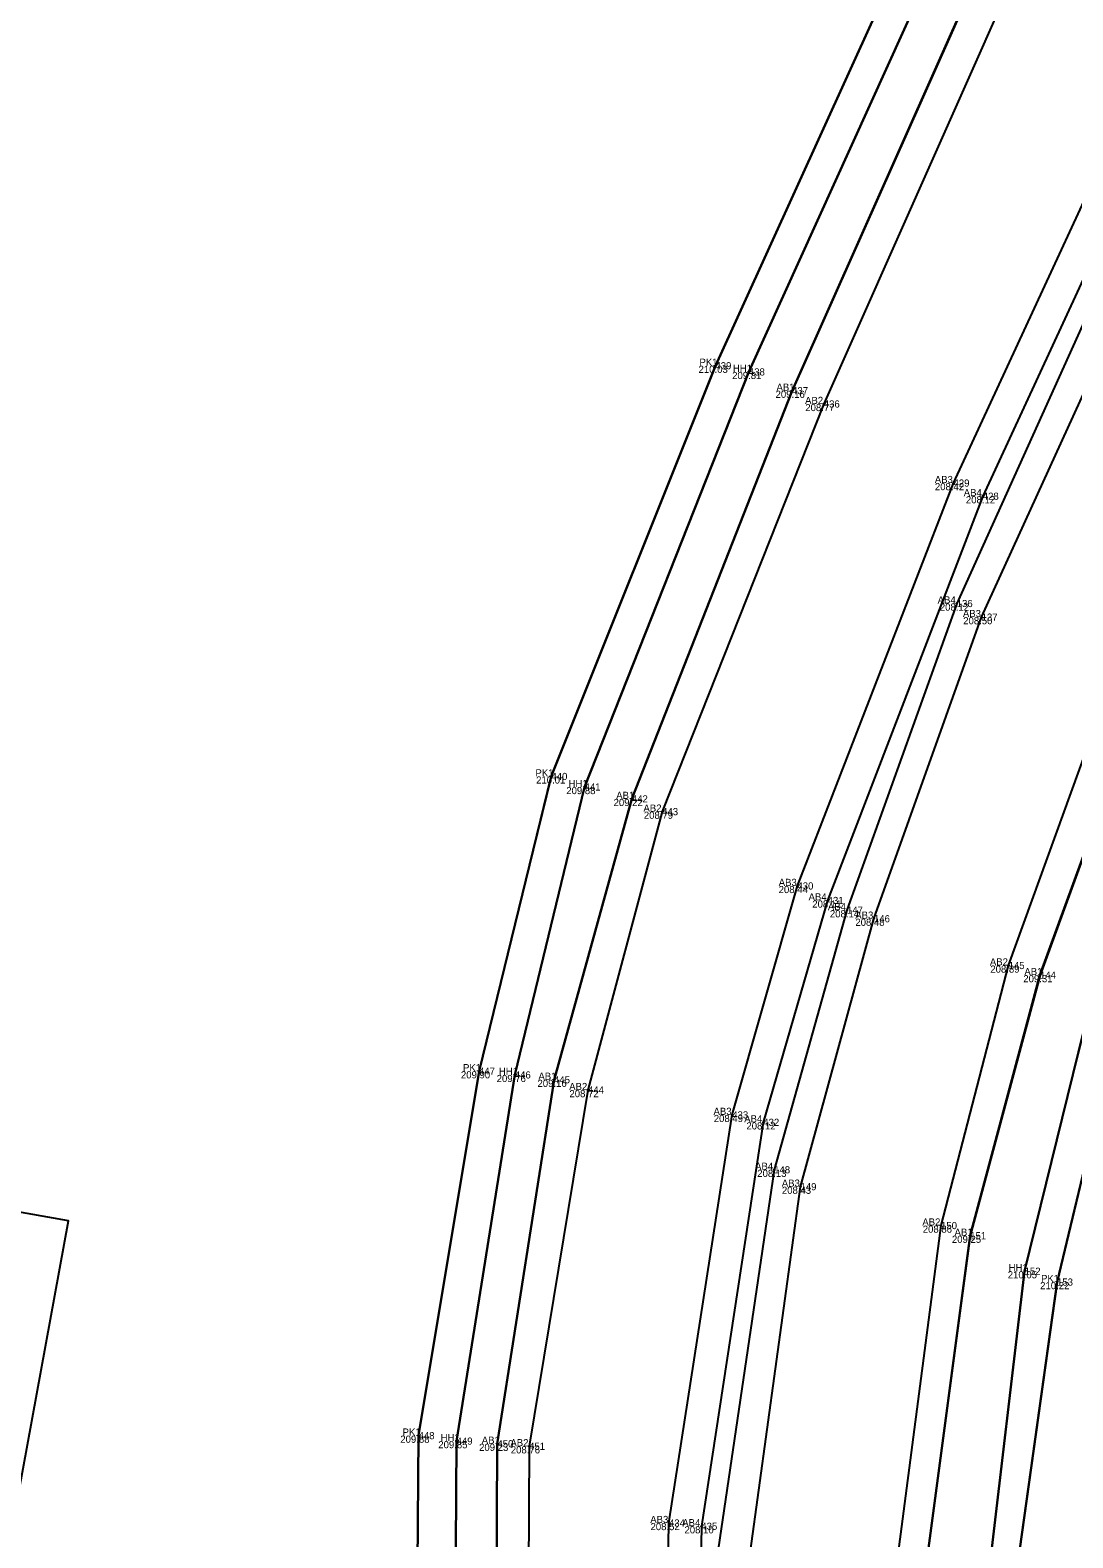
# Model space of a CAD drawing. Extents: x -263091 to -262565, y -1238731 to -1237092.
# Drawn here: x -262822.43 to -262793.24, y -1237721.96 to -1237679.73 of the extents above; entities that cross this region are included whole.
import ezdxf

# ---------------------------------------------------------------- set-up
doc = ezdxf.new("R2010")
doc.units = 0
for name, color, linetype in [('01_Hrana_betónu', 7, 'Continuous'), ('02_Oplotenie', 7, 'Continuous'), ('05_Hrana_terénu', 7, 'Continuous'), ('11_Hranica_KN', 7, 'Continuous'), ('Groma (21)', 7, 'Continuous'), ('Groma (22)', 7, 'Continuous'), ('Groma (23)', 7, 'Continuous'), ('Groma (24)', 7, 'Continuous'), ('U004_Betónové_panely', 7, 'Continuous'), ('U004_Zeleň_mimo', 7, 'Continuous'), ('U004_Zeleň_vnútro', 7, 'Continuous'), ('U004_Zeleň_zatrávňovač', 7, 'Continuous')]:
    doc.layers.add(name, color=color, linetype=linetype)

msp = doc.modelspace()

# ---------------------------------------------------------------- linework, layer by layer
at = {"layer": '01_Hrana_betónu'}
for points in [[(-262833.49, -1237932.513), (-262832.358, -1237924.572), (-262831.993, -1237918.626), (-262831.904, -1237915.074), (-262831.439, -1237906.309), (-262830.324, -1237884.482), (-262828.859, -1237869.656), (-262826.973, -1237856.487), (-262824.752, -1237845.872), (-262820.768, -1237827.409), (-262815.971, -1237805.011), (-262811.874, -1237785.528), (-262810.073, -1237767.205), (-262809.465, -1237744.209), (-262809.348, -1237719.32), (-262807.762, -1237709.127), (-262805.583, -1237701.261), (-262801.096, -1237689.829), (-262795.064, -1237676.268)], [(-262794.181, -1237676.612), (-262800.21, -1237690.201), (-262804.735, -1237701.618), (-262806.814, -1237709.415), (-262808.46, -1237719.391), (-262808.589, -1237744.23), (-262809.169, -1237767.262), (-262810.977, -1237785.858), (-262815.119, -1237805.286), (-262819.878, -1237827.449), (-262823.898, -1237846.237), (-262826.14, -1237856.747), (-262827.996, -1237869.725), (-262829.453, -1237884.611), (-262830.572, -1237906.318), (-262830.909, -1237915.064), (-262831.044, -1237918.638), (-262831.379, -1237924.623), (-262832.499, -1237932.636), (-262832.416, -1237932.646)], [(-262828.366, -1237932.946), (-262828.106, -1237929.217), (-262827.649, -1237919.578), (-262827.369, -1237915.073), (-262826.968, -1237906.664), (-262825.835, -1237884.909), (-262824.318, -1237870.338), (-262822.252, -1237856.88), (-262820.394, -1237847.242), (-262816.344, -1237828.005), (-262811.527, -1237806.128), (-262807.485, -1237786.652), (-262805.817, -1237767.526), (-262804.904, -1237743.876), (-262804.544, -1237721.54), (-262802.773, -1237710.111), (-262800.948, -1237703.699), (-262796.578, -1237692.416), (-262790.297, -1237678.834), (-262789.671, -1237677.512)], [(-262788.862, -1237677.903), (-262789.612, -1237679.5), (-262795.758, -1237692.783), (-262800.102, -1237704.105), (-262801.904, -1237710.319), (-262803.638, -1237721.631), (-262804.041, -1237743.855), (-262804.886, -1237767.666), (-262806.567, -1237786.84), (-262810.653, -1237806.707), (-262815.575, -1237828.361), (-262819.614, -1237847.41), (-262821.404, -1237856.927), (-262823.638, -1237870.532), (-262825.083, -1237884.947), (-262826.299, -1237906.725), (-262827.242, -1237929.453), (-262827.527, -1237933.008)], [(-262788.441, -1237678.106), (-262789.499, -1237680.304), (-262796.488, -1237695.789), (-262799.561, -1237704.378), (-262801.599, -1237711.648), (-262803.17, -1237722.277), (-262803.523, -1237744.912), (-262804.331, -1237767.555), (-262806.033, -1237786.907), (-262810.428, -1237808.027), (-262815.321, -1237829.941), (-262818.5, -1237845.545), (-262820.865, -1237857.635), (-262822.962, -1237871.266), (-262824.386, -1237885.795), (-262825.49, -1237906.658), (-262826.835, -1237930.337), (-262826.931, -1237933.053)], [(-262825.987, -1237933.123), (-262825.899, -1237930.36), (-262825.137, -1237919.703), (-262824.89, -1237915.193), (-262824.65, -1237906.715), (-262823.596, -1237885.855), (-262822.137, -1237871.403), (-262820.061, -1237857.781), (-262817.692, -1237845.812), (-262814.459, -1237830.149), (-262809.645, -1237808.205), (-262805.191, -1237787.117), (-262803.484, -1237767.641), (-262802.568, -1237744.998), (-262802.266, -1237722.317), (-262800.862, -1237712.121), (-262798.805, -1237704.616), (-262795.791, -1237696.17), (-262788.393, -1237679.964), (-262787.674, -1237678.477)], [(-262783.803, -1237680.361), (-262791.072, -1237697.733), (-262794.156, -1237706.196), (-262796.111, -1237713.494), (-262797.353, -1237722.795), (-262798.006, -1237745.028), (-262798.995, -1237767.834), (-262800.837, -1237788.066), (-262805.174, -1237808.895), (-262810.048, -1237831.05), (-262813.207, -1237846.368), (-262815.438, -1237858.025), (-262817.519, -1237871.503), (-262819.01, -1237885.889), (-262819.761, -1237906.843), (-262819.991, -1237915.564)], [(-262820.488, -1237916.085), (-262820.893, -1237915.574), (-262820.599, -1237906.725), (-262819.894, -1237885.916), (-262818.364, -1237871.361), (-262816.365, -1237858.042), (-262814.122, -1237846.343), (-262810.891, -1237830.85), (-262806.137, -1237808.69), (-262801.736, -1237787.923), (-262799.952, -1237767.772), (-262798.979, -1237744.912), (-262798.159, -1237722.635), (-262796.927, -1237713.21), (-262795.035, -1237705.927), (-262791.963, -1237697.425), (-262785.076, -1237681.215)]]:
    msp.add_lwpolyline(points, dxfattribs=at)
at = {"layer": '02_Oplotenie'}
for points in [[(-262834.343, -1237921.203), (-262834.024, -1237915.302), (-262833.812, -1237906.279), (-262832.732, -1237884.616), (-262831.151, -1237869.343), (-262829.251, -1237856.325), (-262826.951, -1237845.31), (-262823.094, -1237827.731), (-262817.951, -1237804.339), (-262814.023, -1237784.135), (-262812.336, -1237767.05), (-262811.754, -1237744.594), (-262811.555, -1237719.093), (-262809.863, -1237708.888), (-262807.835, -1237700.632), (-262803.244, -1237689.13), (-262797.291, -1237676.038)], [(-262782.476, -1237683.046), (-262789.338, -1237700.035), (-262791.92, -1237707.468), (-262793.68, -1237714.792), (-262794.853, -1237723.195), (-262795.698, -1237745.299), (-262796.564, -1237768.081), (-262798.719, -1237788.188), (-262802.852, -1237809.448), (-262807.527, -1237831.589), (-262810.764, -1237846.834), (-262812.842, -1237857.763), (-262814.888, -1237871.127), (-262816.319, -1237886.182), (-262816.945, -1237895.233), (-262817.687, -1237906.993), (-262818.366, -1237915.571), (-262818.764, -1237925.136)]]:
    msp.add_lwpolyline(points, dxfattribs=at)
at = {"layer": '05_Hrana_terénu'}
for points in [[(-262796.037, -1237675.468), (-262802.307, -1237689.303), (-262806.908, -1237700.928), (-262808.861, -1237708.991), (-262810.491, -1237719.246), (-262810.648, -1237744.371), (-262811.212, -1237767.185), (-262812.78, -1237784.48), (-262817.048, -1237804.549), (-262821.958, -1237827.467), (-262825.893, -1237845.536), (-262828.436, -1237856.363), (-262830.087, -1237869.518), (-262831.495, -1237884.449), (-262832.703, -1237906.272), (-262832.889, -1237914.228), (-262832.974, -1237914.835)], [(-262819.123, -1237925.833), (-262819.193, -1237924.361), (-262818.874, -1237915.472), (-262818.289, -1237906.84), (-262817.033, -1237886.241), (-262815.506, -1237871.209), (-262813.693, -1237857.604), (-262811.493, -1237846.649), (-262808.389, -1237831.401), (-262803.328, -1237809.401), (-262799.108, -1237788.219), (-262797.264, -1237767.972), (-262796.32, -1237745.233), (-262795.609, -1237723.113), (-262794.587, -1237714.488), (-262792.775, -1237707.13), (-262790.198, -1237699.936), (-262783.238, -1237683.427), (-262781.933, -1237681.667), (-262781.499, -1237681.254)]]:
    msp.add_lwpolyline(points, dxfattribs=at)
at = {"layer": '11_Hranica_KN'}
msp.add_lwpolyline([(-262860.57, -1237917.21), (-262859.39, -1237895.81), (-262865.89, -1237895.46), (-262864.07, -1237848.35), (-262863.848, -1237844.551), (-262854.69, -1237845.12), (-262848.93, -1237845.467), (-262849.15, -1237849.66), (-262837.88, -1237850.32), (-262835.06, -1237803.04), (-262846.51, -1237802.23), (-262851.357, -1237801.851), (-262850.83, -1237794.01), (-262846.699, -1237756.584), (-262841.32, -1237757.58), (-262829.89, -1237759.64), (-262821.36, -1237713.08), (-262832.88, -1237711.03), (-262837.415, -1237710.153), (-262826.672, -1237665.044), (-262821.31, -1237667.32), (-262810.29, -1237671.46), (-262808.336, -1237666.357)], dxfattribs=at)
at = {"layer": 'Groma (21)'}
for centre in [(-262803.244, -1237689.13), (-262802.307, -1237689.303), (-262801.096, -1237689.829), (-262800.21, -1237690.201), (-262796.578, -1237692.416), (-262795.758, -1237692.783), (-262796.488, -1237695.789), (-262795.791, -1237696.17), (-262807.835, -1237700.632), (-262806.908, -1237700.928), (-262805.583, -1237701.261), (-262804.735, -1237701.618), (-262800.948, -1237703.699), (-262800.102, -1237704.105), (-262799.561, -1237704.378), (-262798.805, -1237704.616), (-262795.035, -1237705.927), (-262794.156, -1237706.196), (-262809.863, -1237708.888), (-262808.861, -1237708.991), (-262807.762, -1237709.127), (-262806.814, -1237709.415), (-262802.773, -1237710.111), (-262801.904, -1237710.319), (-262801.599, -1237711.648), (-262800.862, -1237712.121), (-262796.927, -1237713.21), (-262796.111, -1237713.494), (-262794.587, -1237714.488), (-262793.68, -1237714.792), (-262811.555, -1237719.093), (-262810.491, -1237719.246), (-262809.348, -1237719.32), (-262808.46, -1237719.391), (-262804.544, -1237721.54), (-262803.638, -1237721.631)]:
    msp.add_circle(centre, 0.01, dxfattribs=at)
at = {"layer": 'U004_Betónové_panely'}
msp.add_lwpolyline([(-262809.47, -1237744.21), (-262809.35, -1237719.32), (-262807.76, -1237709.13), (-262805.58, -1237701.26), (-262801.1, -1237689.83), (-262795.06, -1237676.27), (-262794.18, -1237676.61), (-262793.3, -1237675.76), (-262792.52, -1237674.26), (-262788.97, -1237676.03), (-262788.17, -1237676.43), (-262787.74, -1237676.65), (-262786.97, -1237677.03), (-262783.28, -1237678.88), (-262783.94, -1237680.28), (-262783.8, -1237680.36), (-262791.07, -1237697.73), (-262794.16, -1237706.2), (-262796.11, -1237713.49), (-262797.35, -1237722.8)], dxfattribs=at)
msp.add_lwpolyline([(-262809.47, -1237744.21), (-262809.35, -1237719.32), (-262807.76, -1237709.13), (-262805.58, -1237701.26), (-262801.1, -1237689.83), (-262795.06, -1237676.27), (-262794.18, -1237676.61), (-262793.3, -1237675.76), (-262792.52, -1237674.26), (-262788.97, -1237676.03), (-262788.17, -1237676.43), (-262787.74, -1237676.65), (-262786.97, -1237677.03), (-262783.28, -1237678.88), (-262783.94, -1237680.28), (-262783.8, -1237680.36), (-262791.07, -1237697.73), (-262794.16, -1237706.2), (-262796.11, -1237713.49), (-262797.35, -1237722.8)], dxfattribs=at)
at = {"layer": 'U004_Zeleň_mimo'}
for points in [[(-262829.89, -1237759.64), (-262821.36, -1237713.08), (-262832.88, -1237711.03), (-262837.42, -1237710.15), (-262826.67, -1237665.04), (-262821.31, -1237667.32), (-262810.29, -1237671.46), (-262808.34, -1237666.36), (-262795.54, -1237672.75), (-262797.29, -1237676.04), (-262803.24, -1237689.13), (-262807.84, -1237700.63), (-262809.86, -1237708.89), (-262811.56, -1237719.09), (-262811.75, -1237744.59)], [(-262794.85, -1237723.2), (-262793.68, -1237714.79), (-262791.92, -1237707.47), (-262789.34, -1237700.03), (-262782.48, -1237683.05), (-262781.5, -1237681.25), (-262780.92, -1237680.05), (-262777.93, -1237681.41), (-262780.53, -1237687.57), (-262782.28, -1237691.67), (-262786.62, -1237706.53), (-262791.65, -1237746.49)]]:
    msp.add_lwpolyline(points, dxfattribs=at)
at = {"layer": 'U004_Zeleň_vnútro'}
for points in [[(-262811.75, -1237744.59), (-262811.56, -1237719.09), (-262809.86, -1237708.89), (-262807.84, -1237700.63), (-262803.24, -1237689.13), (-262797.29, -1237676.04), (-262795.54, -1237672.75), (-262794.83, -1237673.1), (-262795.49, -1237674.5), (-262796.13, -1237674.77), (-262796.37, -1237675.19), (-262796.04, -1237675.47), (-262802.31, -1237689.3), (-262806.91, -1237700.93), (-262808.86, -1237708.99), (-262810.49, -1237719.25), (-262810.65, -1237744.37)], [(-262811.75, -1237744.59), (-262811.56, -1237719.09), (-262809.86, -1237708.89), (-262807.84, -1237700.63), (-262803.24, -1237689.13), (-262797.29, -1237676.04), (-262795.54, -1237672.75), (-262794.83, -1237673.1), (-262795.49, -1237674.5), (-262796.13, -1237674.77), (-262796.37, -1237675.19), (-262796.04, -1237675.47), (-262802.31, -1237689.3), (-262806.91, -1237700.93), (-262808.86, -1237708.99), (-262810.49, -1237719.25), (-262810.65, -1237744.37)], [(-262795.61, -1237723.11), (-262794.59, -1237714.49), (-262792.78, -1237707.13), (-262790.2, -1237699.94), (-262783.24, -1237683.43), (-262782.19, -1237681.44), (-262781.5, -1237681.25), (-262782.48, -1237683.05), (-262789.34, -1237700.03), (-262791.92, -1237707.47), (-262793.68, -1237714.79), (-262794.85, -1237723.2)], [(-262795.61, -1237723.11), (-262794.59, -1237714.49), (-262792.78, -1237707.13), (-262790.2, -1237699.94), (-262783.24, -1237683.43), (-262782.19, -1237681.44), (-262781.5, -1237681.25), (-262782.48, -1237683.05), (-262789.34, -1237700.03), (-262791.92, -1237707.47), (-262793.68, -1237714.79), (-262794.85, -1237723.2)]]:
    msp.add_lwpolyline(points, dxfattribs=at)
at = {"layer": 'U004_Zeleň_zatrávňovač'}
for points in [[(-262810.65, -1237744.37), (-262810.49, -1237719.25), (-262808.86, -1237708.99), (-262806.91, -1237700.93), (-262802.31, -1237689.3), (-262796.04, -1237675.47), (-262795.06, -1237676.27), (-262801.1, -1237689.83), (-262805.58, -1237701.26), (-262807.76, -1237709.13), (-262809.35, -1237719.32), (-262809.47, -1237744.21)], [(-262810.65, -1237744.37), (-262810.49, -1237719.25), (-262808.86, -1237708.99), (-262806.91, -1237700.93), (-262802.31, -1237689.3), (-262796.04, -1237675.47), (-262795.06, -1237676.27), (-262801.1, -1237689.83), (-262805.58, -1237701.26), (-262807.76, -1237709.13), (-262809.35, -1237719.32), (-262809.47, -1237744.21)], [(-262797.35, -1237722.8), (-262796.11, -1237713.49), (-262794.16, -1237706.2), (-262791.07, -1237697.73), (-262783.8, -1237680.36), (-262782.96, -1237680.85), (-262783, -1237681.17), (-262782.19, -1237681.44), (-262783.24, -1237683.43), (-262790.2, -1237699.94), (-262792.78, -1237707.13), (-262794.59, -1237714.49), (-262795.61, -1237723.11)], [(-262797.35, -1237722.8), (-262796.11, -1237713.49), (-262794.16, -1237706.2), (-262791.07, -1237697.73), (-262783.8, -1237680.36), (-262782.96, -1237680.85), (-262783, -1237681.17), (-262782.19, -1237681.44), (-262783.24, -1237683.43), (-262790.2, -1237699.94), (-262792.78, -1237707.13), (-262794.59, -1237714.49), (-262795.61, -1237723.11)]]:
    msp.add_lwpolyline(points, dxfattribs=at)

# ---------------------------------------------------------------- texts
at = {"layer": 'Groma (22)'}
for s, p in [('439', (-262803.244, -1237689.23)), ('438', (-262802.307, -1237689.403)), ('437', (-262801.096, -1237689.929)), ('436', (-262800.21, -1237690.301)), ('429', (-262796.578, -1237692.516)), ('428', (-262795.758, -1237692.883)), ('136', (-262796.488, -1237695.889)), ('137', (-262795.791, -1237696.27)), ('440', (-262807.835, -1237700.732)), ('441', (-262806.908, -1237701.028)), ('442', (-262805.583, -1237701.361)), ('443', (-262804.735, -1237701.718)), ('430', (-262800.948, -1237703.799)), ('431', (-262800.102, -1237704.205)), ('147', (-262799.561, -1237704.478)), ('146', (-262798.805, -1237704.716)), ('145', (-262795.035, -1237706.027)), ('144', (-262794.156, -1237706.296)), ('447', (-262809.863, -1237708.988)), ('446', (-262808.861, -1237709.091)), ('445', (-262807.762, -1237709.227)), ('444', (-262806.814, -1237709.515)), ('433', (-262802.773, -1237710.211)), ('432', (-262801.904, -1237710.419)), ('148', (-262801.599, -1237711.748)), ('149', (-262800.862, -1237712.221)), ('150', (-262796.927, -1237713.31)), ('151', (-262796.111, -1237713.594)), ('152', (-262794.587, -1237714.588)), ('153', (-262793.68, -1237714.892)), ('448', (-262811.555, -1237719.193)), ('449', (-262810.491, -1237719.346)), ('450', (-262809.348, -1237719.42)), ('451', (-262808.46, -1237719.491)), ('434', (-262804.544, -1237721.64)), ('435', (-262803.638, -1237721.731))]:
    msp.add_text(s, height=0.2, dxfattribs=at).set_placement(p)
at = {"layer": 'Groma (23)'}
for s, p in [('210.03', (-262803.716, -1237689.33)), ('209.81', (-262802.775, -1237689.503)), ('209.16', (-262801.56, -1237690.029)), ('208.77', (-262800.728, -1237690.401)), ('208.42', (-262797.099, -1237692.616)), ('208.12', (-262796.231, -1237692.983)), ('208.12', (-262796.961, -1237695.989)), ('208.50', (-262796.307, -1237696.37)), ('210.01', (-262808.264, -1237700.832)), ('209.88', (-262807.42, -1237701.128)), ('209.22', (-262806.095, -1237701.461)), ('208.79', (-262805.248, -1237701.818)), ('208.44', (-262801.474, -1237703.899)), ('208.11', (-262800.532, -1237704.305)), ('208.14', (-262800.039, -1237704.578)), ('208.48', (-262799.326, -1237704.816)), ('208.89', (-262795.547, -1237706.127)), ('209.31', (-262794.624, -1237706.396)), ('209.90', (-262810.369, -1237709.088)), ('209.76', (-262809.369, -1237709.191)), ('209.16', (-262808.226, -1237709.327)), ('208.72', (-262807.331, -1237709.615)), ('208.49', (-262803.29, -1237710.311)), ('208.12', (-262802.377, -1237710.519)), ('208.13', (-262802.072, -1237711.848)), ('208.43', (-262801.383, -1237712.321)), ('208.86', (-262797.439, -1237713.41)), ('209.25', (-262796.623, -1237713.694)), ('210.05', (-262795.059, -1237714.688)), ('210.22', (-262794.153, -1237714.992)), ('209.88', (-262812.067, -1237719.293)), ('209.85', (-262811.003, -1237719.446)), ('209.23', (-262809.86, -1237719.52)), ('208.76', (-262808.973, -1237719.591)), ('208.52', (-262805.061, -1237721.74)), ('208.10', (-262804.11, -1237721.831))]:
    msp.add_text(s, height=0.2, dxfattribs=at).set_placement(p)
at = {"layer": 'Groma (24)'}
for s, p in [('PK1', (-262803.691, -1237689.13)), ('HH1', (-262802.754, -1237689.303)), ('AB1', (-262801.534, -1237689.829)), ('AB2', (-262800.734, -1237690.201)), ('AB3', (-262797.102, -1237692.416)), ('AB4', (-262796.292, -1237692.783)), ('AB4', (-262797.022, -1237695.789)), ('AB3', (-262796.315, -1237696.17)), ('PK1', (-262808.282, -1237700.632)), ('HH1', (-262807.355, -1237700.928)), ('AB1', (-262806.021, -1237701.261)), ('AB2', (-262805.259, -1237701.618)), ('AB3', (-262801.472, -1237703.699)), ('AB4', (-262800.636, -1237704.105)), ('AB4', (-262800.095, -1237704.378)), ('AB3', (-262799.329, -1237704.616)), ('AB2', (-262795.559, -1237705.927)), ('AB1', (-262794.594, -1237706.196)), ('PK1', (-262810.31, -1237708.888)), ('HH1', (-262809.308, -1237708.991)), ('AB1', (-262808.2, -1237709.127)), ('AB2', (-262807.338, -1237709.415)), ('AB3', (-262803.297, -1237710.111)), ('AB4', (-262802.438, -1237710.319)), ('AB4', (-262802.133, -1237711.648)), ('AB3', (-262801.386, -1237712.121)), ('AB2', (-262797.451, -1237713.21)), ('AB1', (-262796.549, -1237713.494)), ('HH1', (-262795.034, -1237714.488)), ('PK1', (-262794.127, -1237714.792)), ('PK1', (-262812.002, -1237719.093)), ('HH1', (-262810.938, -1237719.246)), ('AB1', (-262809.786, -1237719.32)), ('AB2', (-262808.984, -1237719.391)), ('AB3', (-262805.068, -1237721.54)), ('AB4', (-262804.172, -1237721.631))]:
    msp.add_text(s, height=0.2, dxfattribs=at).set_placement(p)

doc.saveas('drawing.dxf')
